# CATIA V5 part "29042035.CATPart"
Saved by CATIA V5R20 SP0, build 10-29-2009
Part number: 29042035
Definition: NONE
Nomenclature: 29042035
Source: Unknown
Description: 29042035
Bounding box of the stored display mesh (mm): x -17.5 to 44.548, y -35 to 69.548, z -25 to 25
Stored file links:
  C:\Users\Utente\Desktop\IO LAVORO\3D X SITO CF\X SITO\PLASTICA\RF1\29042035.CATPart
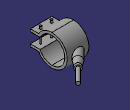
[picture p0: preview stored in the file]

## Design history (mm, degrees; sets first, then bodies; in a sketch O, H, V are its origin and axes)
Body1 "29042035" (main body)
  Solid1: solid without history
